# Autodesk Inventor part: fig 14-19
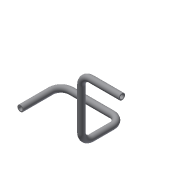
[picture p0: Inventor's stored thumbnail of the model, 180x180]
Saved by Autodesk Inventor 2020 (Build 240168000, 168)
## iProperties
Created: 2005-03
Part Number: fig 14-19
Document SubType Name: Modeling
Designer: CADCIM
Manufacturer: Standard
Standards Organization: Custom
Density: 1 g/cm^3
Material: Generic
Appearance: Default
Author: CADCIM
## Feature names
1. Sweep1
## Parameters: d9 = 6 mm, d10 = 4 mm, d11 = 0, d12 = 0
